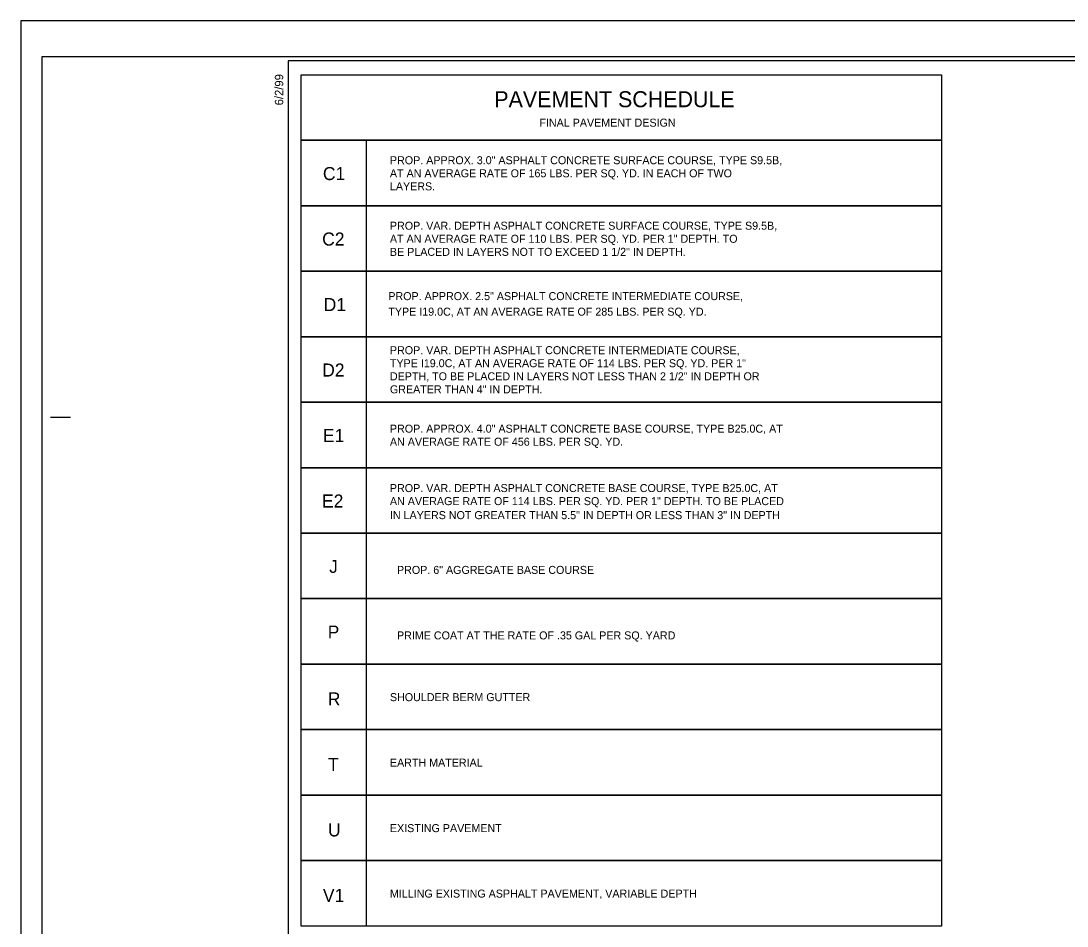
# Model space of a CAD drawing. Extents: x 1497225 to 1499181, y 579958 to 582278.
# Drawn here: x 1497225 to 1497879, y 581713 to 582278 of the extents above; entities that cross this region are included whole.
import ezdxf

# ---------------------------------------------------------------- set-up
doc = ezdxf.new("R2010")
doc.units = 0
for name, color, linetype in [('Prop Pavement Schedule Description CELL', 7, 'Continuous'), ('Sheet Cutting Line CELL', 7, 'Continuous'), ('Sheet Plot Border Inside CELL', 7, 'Continuous'), ('Sheet Plot Border Outside CELL', 7, 'Continuous'), ('Sheet Typical CELL', 7, 'Continuous')]:
    doc.layers.add(name, color=color, linetype=linetype)

msp = doc.modelspace()

# ---------------------------------------------------------------- linework, layer by layer
at = {"layer": 'Prop Pavement Schedule Description CELL'}
msp.add_lwpolyline([(1497400.21, 582244.35), (1497800.21, 582244.35), (1497800.21, 582203.43), (1497400.21, 582203.43)], close=True, dxfattribs=at)
for points in [[(1497441.11, 582162.52), (1497400.21, 582162.52), (1497400.21, 582203.43), (1497800.21, 582203.43), (1497800.21, 582162.52), (1497441.11, 582162.52), (1497441.11, 582203.43)], [(1497441.11, 582121.61), (1497400.21, 582121.61), (1497400.21, 582162.52), (1497800.21, 582162.52), (1497800.21, 582121.61), (1497441.11, 582121.61), (1497441.11, 582162.52)], [(1497441.11, 582080.7), (1497400.21, 582080.7), (1497400.21, 582121.61), (1497800.21, 582121.61), (1497800.21, 582080.7), (1497441.11, 582080.7), (1497441.11, 582121.61)], [(1497441.11, 582039.78), (1497400.21, 582039.78), (1497400.21, 582080.69), (1497800.21, 582080.69), (1497800.21, 582039.78), (1497441.11, 582039.78), (1497441.11, 582080.69)], [(1497441.11, 581998.87), (1497400.21, 581998.87), (1497400.21, 582039.78), (1497800.21, 582039.78), (1497800.21, 581998.87), (1497441.11, 581998.87), (1497441.11, 582039.78)], [(1497441.11, 581957.96), (1497400.21, 581957.96), (1497400.21, 581998.87), (1497800.21, 581998.87), (1497800.21, 581957.96), (1497441.11, 581957.96), (1497441.11, 581998.87)], [(1497441.11, 581917.05), (1497400.21, 581917.05), (1497400.21, 581957.96), (1497800.21, 581957.96), (1497800.21, 581917.05), (1497441.11, 581917.05), (1497441.11, 581957.96)], [(1497441.11, 581876.14), (1497400.21, 581876.14), (1497400.21, 581917.05), (1497800.21, 581917.05), (1497800.21, 581876.14), (1497441.11, 581876.14), (1497441.11, 581917.05)], [(1497441.11, 581835.23), (1497400.21, 581835.23), (1497400.21, 581876.14), (1497800.21, 581876.14), (1497800.21, 581835.23), (1497441.11, 581835.23), (1497441.11, 581876.14)], [(1497441.11, 581794.32), (1497400.21, 581794.32), (1497400.21, 581835.23), (1497800.21, 581835.23), (1497800.21, 581794.32), (1497441.11, 581794.32), (1497441.11, 581835.23)], [(1497441.11, 581753.42), (1497400.21, 581753.42), (1497400.21, 581794.32), (1497800.21, 581794.32), (1497800.21, 581753.42), (1497441.11, 581753.42), (1497441.11, 581794.32)], [(1497441.11, 581712.51), (1497400.21, 581712.51), (1497400.21, 581753.42), (1497800.21, 581753.42), (1497800.21, 581712.51), (1497441.11, 581712.51), (1497441.11, 581753.42)]]:
    msp.add_lwpolyline(points, dxfattribs=at)
at = {"layer": 'Sheet Cutting Line CELL'}
for p, q in [((1498909.23, 582277.96), (1497225.23, 582277.96)), ((1497225.23, 582277.96), (1497225.23, 581177.96))]:
    msp.add_line(p, q, dxfattribs=at)
at = {"layer": 'Sheet Plot Border Inside CELL'}
msp.add_lwpolyline([(1498904.73, 582255.51), (1497238.23, 582255.51), (1497238.23, 581200.41), (1498904.73, 581200.41)], close=True, dxfattribs=at)
at = {"layer": 'Sheet Plot Border Outside CELL'}
msp.add_lwpolyline([(1498909.23, 582277.96), (1497225.23, 582277.96), (1497225.23, 581177.96), (1498909.23, 581177.96)], close=True, dxfattribs=at)
at = {"layer": 'Sheet Typical CELL'}
msp.add_line((1497243.73, 582030.46), (1497256.23, 582030.46), dxfattribs=at)
msp.add_lwpolyline([(1498892.23, 582252.96), (1497392.23, 582252.96), (1497392.23, 581202.96), (1498892.23, 581202.96)], close=True, dxfattribs=at)

# ---------------------------------------------------------------- texts
at = {"layer": 'Prop Pavement Schedule Description CELL'}
for s, height, p in [('PAVEMENT SCHEDULE', 10, (1497520.9, 582224.04)), ('FINAL PAVEMENT DESIGN', 5, (1497549.06, 582211.9)), ('PROP. APPROX. 3.0" ASPHALT CONCRETE SURFACE COURSE, TYPE S9.5B, ', 5, (1497455.7, 582188.43)), ('C1', 8.167, (1497413.84, 582178.52)), ('AT AN AVERAGE RATE OF 165 LBS. PER SQ. YD. IN EACH OF TWO ', 5, (1497455.7, 582180.27)), ('LAYERS.', 5, (1497455.7, 582172.12)), ('PROP. VAR. DEPTH ASPHALT CONCRETE SURFACE COURSE, TYPE S9.5B,', 5, (1497455.7, 582147.52)), ('C2', 8.167, (1497413.39, 582137.61)), ('AT AN AVERAGE RATE OF 110 LBS. PER SQ. YD. PER 1" DEPTH. TO', 5, (1497455.7, 582139.36)), ('BE PLACED IN LAYERS NOT TO EXCEED 1 1/2" IN DEPTH.', 5, (1497455.7, 582131.2)), ('PROP. APPROX. 2.5" ASPHALT CONCRETE INTERMEDIATE COURSE,', 5, (1497454.7, 582103.54)), ('D1', 8.167, (1497414.34, 582096.69)), ('TYPE I19.0C, AT AN AVERAGE RATE OF 285 LBS. PER SQ. YD.', 5, (1497454.7, 582093.81)), ('PROP. VAR. DEPTH ASPHALT CONCRETE INTERMEDIATE COURSE,', 5, (1497455.7, 582069.77)), ('D2', 8.167, (1497413.39, 582055.78)), ('TYPE I19.0C, AT AN AVERAGE RATE OF 114 LBS. PER SQ. YD. PER 1" ', 5, (1497455.7, 582061.62)), ('DEPTH, TO BE PLACED IN LAYERS NOT LESS THAN 2 1/2" IN DEPTH OR', 5, (1497455.7, 582053.46)), ('GREATER THAN 4" IN DEPTH.', 5, (1497455.7, 582045.3)), ('E1', 8.167, (1497413.84, 582014.87)), ('PROP. APPROX. 4.0" ASPHALT CONCRETE BASE COURSE, TYPE B25.0C, AT', 5, (1497455.7, 582020.74)), ('AN AVERAGE RATE OF 456 LBS. PER SQ. YD.', 5, (1497455.7, 582012.58)), ('PROP. VAR. DEPTH ASPHALT CONCRETE BASE COURSE, TYPE B25.0C, AT', 5, (1497455.7, 581983.63)), ('E2', 8.167, (1497413.27, 581973.95)), ('AN AVERAGE RATE OF 114 LBS. PER SQ. YD. PER 1" DEPTH. TO BE PLACED ', 5, (1497455.7, 581975.47)), ('IN LAYERS NOT GREATER THAN 5.5" IN DEPTH OR LESS THAN 3" IN DEPTH', 5, (1497455.7, 581966.72)), ('J', 8, (1497417.78, 581933.13)), ('PROP. 6" AGGREGATE BASE COURSE', 5, (1497460.12, 581932.5)), ('P', 8, (1497416.92, 581892.22)), ('PRIME COAT AT THE RATE OF .35 GAL PER SQ. YARD', 5, (1497460.12, 581891.59)), ('R', 8.17, (1497416.91, 581850.32)), ('SHOULDER BERM GUTTER', 5, (1497455.7, 581853.02)), ('T', 8.17, (1497417.02, 581809.41)), ('EARTH MATERIAL', 5, (1497455.7, 581812.11)), ('U', 8.17, (1497417.02, 581768.5)), ('EXISTING PAVEMENT', 5, (1497455.7, 581771.2)), ('V1', 8.167, (1497413.84, 581727.59)), ('MILLING EXISTING ASPHALT PAVEMENT, VARIABLE DEPTH', 5, (1497455.7, 581730.29))]:
    msp.add_text(s, height=height, dxfattribs=at).set_placement(p)
at = {"layer": 'Sheet Typical CELL'}
msp.add_text('6/2/99', height=5.25, rotation=90, dxfattribs=at).set_placement((1497389.08, 582225.21))

doc.saveas('drawing.dxf')
